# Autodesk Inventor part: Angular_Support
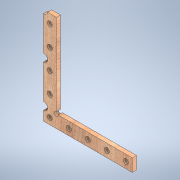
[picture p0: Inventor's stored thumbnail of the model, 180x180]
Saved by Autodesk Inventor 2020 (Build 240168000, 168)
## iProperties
Created: 2020-02
Part Number: Angular_Support
Material: Wood (Birch)
Document SubType Name: Modeling
Designer: mmg
Density: 0.55 g/cm^3
Appearance: Birch - Natural Polished
Mass: 283.492 g
Surface Area: 953.696 cm^2
Volume: 515.441 cm^3
Author: mmg
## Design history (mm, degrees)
sketch "Sketch1"
  geometry: L1 (0, 0)-(350, 0); L2 (350, 0)-(350, 50); L3 (350, 50)-(57.5, 50); L4 (0, 50)-(0, 0); L5 (50, 380)-(0, 380); L6 (0, 380)-(0, 50); L7 (50, 380)-(50, 57.5); A1 r 7.5 centre (50, 50) between (50, 57.5) and (57.5, 50)
  constraints: 14 end point, 2 parallel, 2 point on circle, 1 centre point, 1 horizontal, 1 perpendicular, 1 vertical
  dimensions: "d3" = 50 distance of L2.end L1.end; "d8" = 50 distance of L5.start L5.end; "d9" = 15 diameter of A1; "d13" = 322.5 distance of L5.start L7.end; "d14" = 292.5 distance of L2.end L3.end; "d15" = 350 distance of L1.start L1.end; "d47" = 380 distance between parallel lines of L1 L5
extrude "Extrusion1" new body sketch "Sketch1" distance "d16" = 16.3; taper "d17" = 0 deg
sketch "Sketch2"
  geometry: L1 (0, 0)-(350, 0) reference; L2 (0, 380)-(0, 0) reference; 1 further point
  dimensions: "d18" = 25 distance from line of L1 point (25, 25); "d19" = 25 distance from line of L2 point (25, 25)
hole "Hole1" sketch "Sketch2" at (25, 25) diameter "d20" = 8; stored, may be unused: countersink angle "d24" = 90 deg, drill point angle "d26" = 118 deg; dims "d21" = 6, "d22" = 4, "d23" = 2, "d25" = 8
pattern_linear "Rectangular Pattern1" dims "d29" = 75
pattern_linear "Rectangular Pattern2" dims "d32" = 80
sketch "Sketch3"
  geometry: C1 r 4 at (25, 25) reference; C2 r 10 at (25, 25); 1 further point
  constraints: 1 centre point, 1 coincident
  dimensions: "d33" = 20 diameter of C2
extrude "Extrusion2" cut sketch "Sketch3" distance "d34" = 6; taper "d35" = 0 deg
pattern_linear "Rectangular Pattern3" dims "d38" = 80
pattern_linear "Rectangular Pattern4" dims "d41" = 75
sketch "Sketch4"
  geometry: C1 r 15 at (1, 52.5); C2 r 4 at (25, 25) reference; 1 further point
  constraints: 1 centre point
  dimensions: "d42" = 30 diameter of C1; "d43" = 27.5 vertical distance of C2.centre C1.centre; "d44" = 24 horizontal distance of C2.centre C1.centre
extrude "Extrusion3" cut sketch "Sketch4" extent not by distance; stored distance "d45" = 0; taper "d46" = 0 deg
pattern_linear "Rectangular Pattern5" dims "d50" = 165
body "Solid1"
